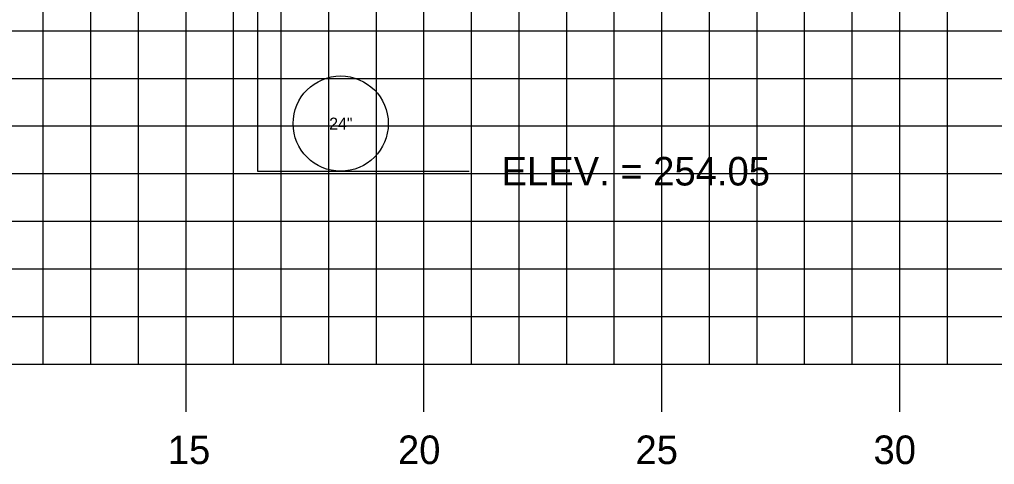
# Model space of a CAD drawing. Extents: x 856235 to 856405, y 366268 to 366378.
# Drawn here: x 856329.28 to 856349.77, y 366351.37 to 366360.72 of the extents above; entities that cross this region are included whole.
import ezdxf

# ---------------------------------------------------------------- set-up
doc = ezdxf.new("R2010")
doc.units = 0
for name, color, linetype in [('D_Text_Standard', 7, 'Continuous'), ('H_V ANNOTATION', 7, 'Continuous'), ('junk strct exc', 7, 'Continuous'), ('MAJOR', 7, 'Continuous'), ('MINOR', 7, 'Continuous'), ('PDRAIN', 7, 'Continuous')]:
    doc.layers.add(name, color=color, linetype=linetype)

msp = doc.modelspace()

# ---------------------------------------------------------------- linework, layer by layer
at = {"layer": 'D_Text_Standard'}
msp.add_lwpolyline([(856337.781, 366357.531), (856338.05, 366357.531), (856338.73, 366357.531)], dxfattribs=at)
at = {"layer": 'junk strct exc'}
msp.add_lwpolyline([(856334.281, 366361.461), (856334.281, 366357.531), (856337.781, 366357.531), (856337.781, 366361.391)], close=True, dxfattribs=at)
at = {"layer": 'MAJOR'}
for p, q in [((856332.781, 366353.481), (856332.781, 366373.481)), ((856337.781, 366353.481), (856337.781, 366373.481)), ((856342.781, 366353.481), (856342.781, 366373.481)), ((856347.781, 366353.481), (856347.781, 366373.481)), ((856247.781, 366358.481), (856387.781, 366358.481)), ((856247.781, 366353.481), (856387.781, 366353.481)), ((856247.781, 366353.481), (856387.781, 366353.481)), ((856332.781, 366352.479), (856332.781, 366353.481)), ((856337.781, 366352.479), (856337.781, 366353.481)), ((856342.781, 366352.479), (856342.781, 366353.481)), ((856347.781, 366352.479), (856347.781, 366353.481))]:
    msp.add_line(p, q, dxfattribs=at)
at = {"layer": 'MINOR'}
for p, q in [((856329.781, 366353.481), (856329.781, 366373.481)), ((856330.781, 366353.481), (856330.781, 366373.481)), ((856331.781, 366353.481), (856331.781, 366373.481)), ((856333.781, 366353.481), (856333.781, 366373.481)), ((856334.781, 366353.481), (856334.781, 366373.481)), ((856335.781, 366353.481), (856335.781, 366373.481)), ((856336.781, 366353.481), (856336.781, 366373.481)), ((856338.781, 366353.481), (856338.781, 366373.481)), ((856339.781, 366353.481), (856339.781, 366373.481)), ((856340.781, 366353.481), (856340.781, 366373.481)), ((856341.781, 366353.481), (856341.781, 366373.481)), ((856343.781, 366353.481), (856343.781, 366373.481)), ((856344.781, 366353.481), (856344.781, 366373.481)), ((856345.781, 366353.481), (856345.781, 366373.481)), ((856346.781, 366353.481), (856346.781, 366373.481)), ((856348.781, 366353.481), (856348.781, 366373.481)), ((856247.781, 366360.481), (856387.781, 366360.481)), ((856247.781, 366359.481), (856387.781, 366359.481)), ((856247.781, 366357.481), (856387.781, 366357.481)), ((856247.781, 366356.481), (856387.781, 366356.481)), ((856247.781, 366355.481), (856387.781, 366355.481)), ((856247.781, 366354.481), (856387.781, 366354.481))]:
    msp.add_line(p, q, dxfattribs=at)
at = {"layer": 'PDRAIN'}
msp.add_lwpolyline([(856334.281, 366361.461), (856334.281, 366357.531), (856337.781, 366357.531), (856337.781, 366361.391)], dxfattribs=at)
msp.add_circle((856336.031, 366358.531), 1, dxfattribs=at)

# ---------------------------------------------------------------- texts
at = {"layer": 'D_Text_Standard'}
msp.add_text('ELEV. = 254.05', height=0.6, dxfattribs=at).set_placement((856339.41, 366357.231))
at = {"layer": 'H_V ANNOTATION'}
for s, p in [('15', (856332.398, 366351.381)), ('20', (856337.235, 366351.381)), ('25', (856342.227, 366351.381)), ('30', (856347.229, 366351.381))]:
    msp.add_text(s, height=0.6, dxfattribs=at).set_placement(p)
at = {"layer": 'PDRAIN'}
msp.add_text('24"', height=0.25, dxfattribs=at).set_placement((856335.789, 366358.406))

doc.saveas('drawing.dxf')
